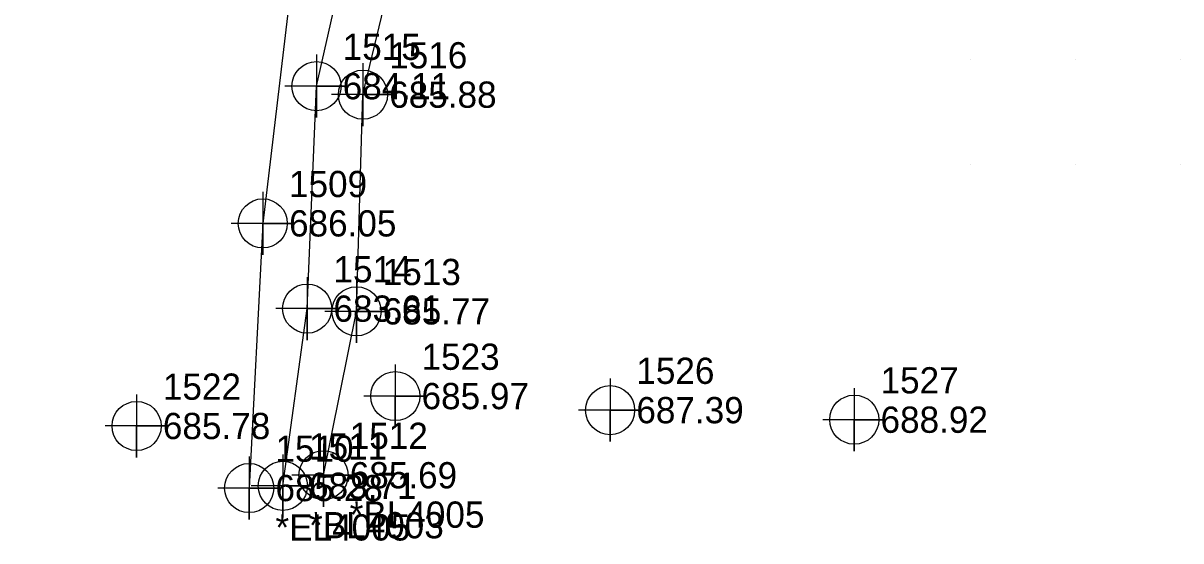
# Model space of a CAD drawing. Extents: x 1755643 to 1760494, y 736519 to 737621.
# Drawn here: x 1757975.2 to 1758085.4, y 736839.1 to 736888.4 of the extents above; entities that cross this region are included whole.
import ezdxf

# ---------------------------------------------------------------- set-up
doc = ezdxf.new("R2010")
doc.units = 0
for name, color, linetype in [('Exist Horizontal Alignment Curve and Spiral Data', 7, 'Continuous'), ('Exist Horizontal Alignment Direction Label', 7, 'Continuous'), ('Exist Roads EOT', 7, 'Continuous'), ('Old_Level_1', 7, 'Continuous'), ('Old_Level_10', 7, 'Continuous'), ('Old_Level_2', 7, 'Continuous'), ('Old_Level_3', 7, 'Continuous'), ('Prop Dimension', 7, 'Continuous'), ('Prop EOT Dash', 7, 'Continuous'), ('Prop Horizontal Alignment Direction Label', 7, 'Continuous'), ('Prop Lane Lines', 7, 'Continuous'), ('Prop Paint Stripe', 7, 'Continuous'), ('Prop Paved Shoulder', 7, 'Continuous'), ('Scratch_Level_9', 7, 'Continuous')]:
    doc.layers.add(name, color=color, linetype=linetype)

msp = doc.modelspace()

# ---------------------------------------------------------------- linework, layer by layer
at = {"layer": 'Exist Horizontal Alignment Curve and Spiral Data'}
for points in [[(1758010.61, 736855.87), (1758010.61, 736849.87), (1758010.61, 736852.87), (1758013.61, 736852.87), (1758007.61, 736852.87)], [(1758031.06, 736854.53), (1758031.06, 736848.53), (1758031.06, 736851.53), (1758034.06, 736851.53), (1758028.06, 736851.53)], [(1758054.31, 736853.62), (1758054.31, 736847.62), (1758054.31, 736850.62), (1758057.31, 736850.62), (1758051.31, 736850.62)], [(1757985.98, 736853.02), (1757985.98, 736847.02), (1757985.98, 736850.02), (1757988.98, 736850.02), (1757982.98, 736850.02)]]:
    msp.add_lwpolyline(points, dxfattribs=at)
for centre in [(1758010.61, 736852.87), (1758031.06, 736851.53), (1758054.31, 736850.62), (1757985.98, 736850.02)]:
    msp.add_circle(centre, 2.34, dxfattribs=at)
at = {"layer": 'Old_Level_10'}
for points in [[(1758003.1, 736885.39), (1758003.1, 736879.39), (1758003.1, 736882.39), (1758006.1, 736882.39), (1758000.1, 736882.39)], [(1758002.22, 736864.2), (1758002.22, 736858.2), (1758002.22, 736861.2), (1758005.22, 736861.2), (1757999.22, 736861.2)], [(1757999.9, 736847.32), (1757999.9, 736841.32), (1757999.9, 736844.32), (1758002.9, 736844.32), (1757996.9, 736844.32)]]:
    msp.add_lwpolyline(points, dxfattribs=at)
for centre in [(1758003.1, 736882.39), (1758002.22, 736861.2), (1757999.9, 736844.32)]:
    msp.add_circle(centre, 2.34, dxfattribs=at)
at = {"layer": 'Prop Dimension'}
msp.add_lwpolyline([(1757999.9, 736844.32), (1758002.22, 736861.2), (1758003.1, 736882.39), (1758005.62, 736893.5)], dxfattribs=at)
at = {"layer": 'Prop Lane Lines'}
for points in [[(1758007.53, 736884.58), (1758007.53, 736878.58), (1758007.53, 736881.58), (1758010.53, 736881.58), (1758004.53, 736881.58)], [(1757997.99, 736872.32), (1757997.99, 736866.32), (1757997.99, 736869.32), (1758000.99, 736869.32), (1757994.99, 736869.32)], [(1758006.91, 736863.94), (1758006.91, 736857.94), (1758006.91, 736860.94), (1758009.91, 736860.94), (1758003.91, 736860.94)], [(1758003.77, 736848.33), (1758003.77, 736842.33), (1758003.77, 736845.33), (1758006.77, 736845.33), (1758000.77, 736845.33)], [(1757996.7, 736847.11), (1757996.7, 736841.11), (1757996.7, 736844.11), (1757999.7, 736844.11), (1757993.7, 736844.11)]]:
    msp.add_lwpolyline(points, dxfattribs=at)
for centre in [(1758007.53, 736881.58), (1757997.99, 736869.32), (1758006.91, 736860.94), (1758003.77, 736845.33), (1757996.7, 736844.11)]:
    msp.add_circle(centre, 2.34, dxfattribs=at)
at = {"layer": 'Prop Paint Stripe'}
for p, q in [((1758065.4, 736884.97), (1758065.4, 736884.97)), ((1758075.4, 736884.97), (1758075.4, 736884.97)), ((1758085.4, 736884.97), (1758085.4, 736884.97)), ((1758065.4, 736874.97), (1758065.4, 736874.97)), ((1758075.4, 736874.97), (1758075.4, 736874.97)), ((1758085.4, 736874.97), (1758085.4, 736874.97))]:
    msp.add_line(p, q, dxfattribs=at)
at = {"layer": 'Scratch_Level_9'}
for points in [[(1758003.77, 736845.33), (1758006.91, 736860.94), (1758007.53, 736881.58), (1758010.42, 736893.61), (1758010.46, 736912.32), (1758010.06, 736936.56), (1758010.2, 736961.18), (1758017.95, 736966.34), (1758033.33, 736970.7), (1758040.24, 736972.09)], [(1757948.28, 736970.45), (1757979.41, 736971.2), (1757997.7, 736970.69), (1757996.98, 736960.28), (1758000.48, 736938.14), (1758002.68, 736915.64), (1758001.11, 736895.52), (1757997.99, 736869.32), (1757996.7, 736844.11)]]:
    msp.add_lwpolyline(points, dxfattribs=at)

# ---------------------------------------------------------------- texts
at = {"layer": 'Exist Horizontal Alignment Direction Label'}
for s, p in [('*BL4005', (1758006.27, 736840.33)), ('*EL4005', (1757999.2, 736839.11))]:
    msp.add_text(s, height=2.5, dxfattribs=at).set_placement(p)
at = {"layer": 'Exist Roads EOT'}
for s, p in [('1523', (1758013.11, 736855.37)), ('1526', (1758033.56, 736854.03)), ('1522', (1757988.48, 736852.52)), ('1527', (1758056.81, 736853.12))]:
    msp.add_text(s, height=2.5, dxfattribs=at).set_placement(p)
at = {"layer": 'Old_Level_1'}
for s, p in [('1515', (1758005.6, 736884.89)), ('1514', (1758004.72, 736863.7)), ('1511', (1758002.4, 736846.82))]:
    msp.add_text(s, height=2.5, dxfattribs=at).set_placement(p)
at = {"layer": 'Old_Level_2'}
for s, p in [('684.11', (1758005.6, 736881.14)), ('683.61', (1758004.72, 736859.95)), ('683.71', (1758002.4, 736843.07))]:
    msp.add_text(s, height=2.5, dxfattribs=at).set_placement(p)
at = {"layer": 'Old_Level_3'}
for s, p in [('685.88', (1758010.03, 736880.33)), ('686.05', (1758000.49, 736868.07)), ('685.77', (1758009.41, 736859.69)), ('685.69', (1758006.27, 736844.08)), ('685.28', (1757999.2, 736842.86))]:
    msp.add_text(s, height=2.5, dxfattribs=at).set_placement(p)
at = {"layer": 'Prop EOT Dash'}
for s, p in [('1516', (1758010.03, 736884.08)), ('1509', (1758000.49, 736871.82)), ('1513', (1758009.41, 736863.44)), ('1512', (1758006.27, 736847.83)), ('1510', (1757999.2, 736846.61))]:
    msp.add_text(s, height=2.5, dxfattribs=at).set_placement(p)
at = {"layer": 'Prop Horizontal Alignment Direction Label'}
msp.add_text('*BL4003', height=2.5, dxfattribs=at).set_placement((1758002.4, 736839.32))
at = {"layer": 'Prop Paved Shoulder'}
for s, p in [('685.97', (1758013.11, 736851.62)), ('687.39', (1758033.56, 736850.28)), ('688.92', (1758056.81, 736849.37)), ('685.78', (1757988.48, 736848.77))]:
    msp.add_text(s, height=2.5, dxfattribs=at).set_placement(p)

doc.saveas('drawing.dxf')
